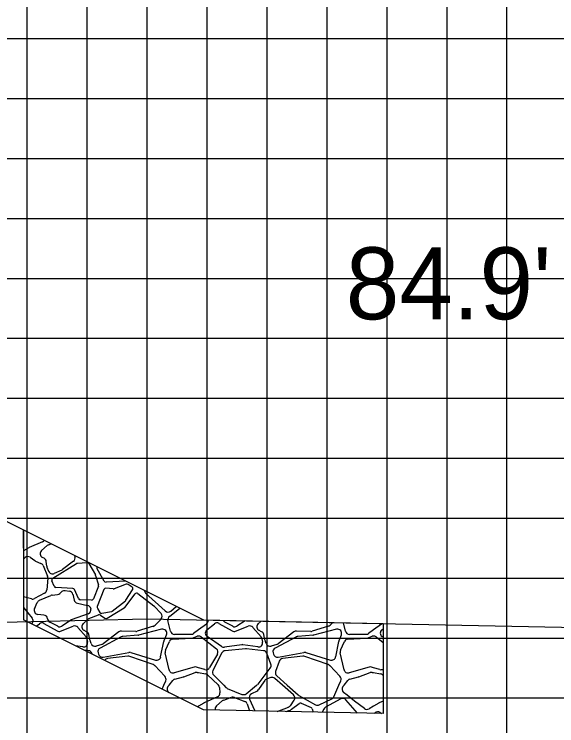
# Model space of a CAD drawing. Extents: x 1785795 to 1786139, y 442591 to 442811.
# Drawn here: x 1786039.83 to 1786048.88, y 442680.2 to 442692.07 of the extents above; entities that cross this region are included whole.
import ezdxf

# ---------------------------------------------------------------- set-up
doc = ezdxf.new("R2010")
doc.units = 0
for name, color, linetype in [('D_Roadway_Centerline', 7, 'Continuous'), ('D_Roadway_SlopeLines', 7, 'Continuous'), ('D_Text_Standard', 7, 'Continuous'), ('MAJOR', 7, 'Continuous'), ('MINOR', 7, 'Continuous'), ('S_Roadway_Centerline', 7, 'Continuous')]:
    doc.layers.add(name, color=color, linetype=linetype)

msp = doc.modelspace()

# ---------------------------------------------------------------- linework, layer by layer
at = {"layer": 'D_Roadway_Centerline'}
msp.add_lwpolyline([(1785883.536, 442683.648), (1785933.236, 442708.498), (1785938.052, 442710.906), (1785941.052, 442711.026), (1785949.052, 442711.346), (1785961.052, 442711.61), (1785973.052, 442711.874), (1785981.052, 442711.554), (1785984.052, 442711.434), (1785988.802, 442709.059), (1786042.988, 442681.966)], dxfattribs=at)
at = {"layer": 'D_Roadway_SlopeLines'}
for p, q in [((1786040.305, 442683.272), (1786040.082, 442683.173)), ((1786040.075, 442683.169), (1786039.988, 442683.117)), ((1786040.289, 442683.123), (1786040.385, 442683.207)), ((1786040.408, 442683.221), (1786040.451, 442683.235)), ((1786040.841, 442683.04), (1786040.847, 442683.022)), ((1786039.988, 442682.983), (1786040.015, 442683.007)), ((1786040.1, 442683.012), (1786040.178, 442682.956)), ((1786040.19, 442682.949), (1786040.28, 442682.91)), ((1786040.332, 442682.996), (1786040.302, 442683.011)), ((1786040.375, 442682.865), (1786040.368, 442682.941)), ((1786040.823, 442682.945), (1786040.639, 442682.806)), ((1786040.89, 442682.911), (1786041.045, 442682.924)), ((1786040.315, 442682.874), (1786040.389, 442682.696)), ((1786040.409, 442682.777), (1786040.381, 442682.844)), ((1786040.477, 442682.662), (1786040.875, 442682.906)), ((1786040.626, 442682.798), (1786040.5, 442682.742)), ((1786041.077, 442682.907), (1786041.189, 442682.718)), ((1786041.333, 442682.614), (1786041.215, 442682.821)), ((1786041.192, 442682.71), (1786041.24, 442682.552)), ((1786040.394, 442682.664), (1786040.376, 442682.468)), ((1786040.5, 442682.53), (1786040.463, 442682.619)), ((1786041.693, 442682.614), (1786041.365, 442682.596)), ((1786041.702, 442682.562), (1786041.5, 442682.487)), ((1786041.8, 442682.514), (1786041.733, 442682.559)), ((1786040.812, 442682.493), (1786040.53, 442682.509)), ((1786040.592, 442682.407), (1786040.63, 442682.439)), ((1786040.681, 442682.455), (1786040.753, 442682.447)), ((1786040.907, 442682.322), (1786040.841, 442682.472)), ((1786041.239, 442682.529), (1786041.155, 442682.317)), ((1786041.329, 442682.475), (1786041.219, 442682.19)), ((1786041.485, 442682.485), (1786041.364, 442682.497)), ((1786041.695, 442682.296), (1786041.809, 442682.467)), ((1786040.12, 442682.317), (1786039.988, 442682.352)), ((1786040.34, 442682.414), (1786040.17, 442682.323)), ((1786040.255, 442682.294), (1786040.447, 442682.375)), ((1786040.465, 442682.379), (1786040.556, 442682.391)), ((1786040.813, 442682.394), (1786040.834, 442682.297)), ((1786041.677, 442682.176), (1786041.849, 442682.4)), ((1786041.897, 442682.407), (1786042.163, 442682.203)), ((1786042.026, 442682.413), (1786042.354, 442682.116)), ((1786040.173, 442682.154), (1786040.218, 442682.259)), ((1786040.887, 442682.245), (1786041.058, 442682.21)), ((1786041.122, 442682.296), (1786040.937, 442682.302)), ((1786041.469, 442682.112), (1786041.688, 442682.288)), ((1786042.167, 442682.199), (1786042.282, 442682.074)), ((1786039.988, 442682.173), (1786040.133, 442681.995)), ((1786041.11, 442682.158), (1786041.113, 442682.147)), ((1786041.222, 442682.16), (1786041.262, 442682.093)), ((1786041.297, 442682.077), (1786041.454, 442682.105)), ((1786041.384, 442681.994), (1786041.668, 442682.167)), ((1786042.421, 442682.025), (1786042.595, 442682.163)), ((1786042.444, 442682.115), (1786042.533, 442682.193)), ((1786040.33, 442682.048), (1786040.228, 442682.059)), ((1786040.391, 442681.984), (1786040.39, 442681.988)), ((1786040.788, 442681.966), (1786040.629, 442681.864)), ((1786041.069, 442682.067), (1786040.802, 442681.973)), ((1786040.984, 442681.904), (1786041.069, 442681.981)), ((1786041.08, 442681.988), (1786041.242, 442682.051)), ((1786041.274, 442682.047), (1786041.346, 442681.995)), ((1786042.282, 442681.981), (1786042.184, 442681.878)), ((1786042.988, 442681.966), (1786045.988, 442681.905)), ((1786040.2, 442681.86), (1786040.253, 442681.903)), ((1786040.33, 442681.909), (1786040.548, 442681.783)), ((1786040.56, 442681.861), (1786040.427, 442681.931)), ((1786040.607, 442681.779), (1786040.818, 442681.862)), ((1786040.895, 442681.843), (1786041.032, 442681.683)), ((1786042.154, 442681.86), (1786041.884, 442681.778)), ((1786042.44, 442681.778), (1786042.397, 442681.955)), ((1786043.04, 442681.897), (1786042.906, 442681.799)), ((1786043.046, 442681.802), (1786043.172, 442681.903)), ((1786043.249, 442681.909), (1786043.466, 442681.783)), ((1786043.479, 442681.861), (1786043.346, 442681.931)), ((1786043.526, 442681.779), (1786043.736, 442681.862)), ((1786043.685, 442681.952), (1786043.547, 442681.864)), ((1786043.813, 442681.843), (1786043.951, 442681.683)), ((1786043.903, 442681.904), (1786043.95, 442681.947)), ((1786045.073, 442681.86), (1786044.803, 442681.778)), ((1786045.145, 442681.922), (1786045.102, 442681.878)), ((1786045.359, 442681.778), (1786045.325, 442681.919)), ((1786045.959, 442681.897), (1786045.825, 442681.799)), ((1786045.988, 442681.905), (1786045.988, 442680.405)), ((1786041.042, 442681.77), (1786040.998, 442681.793)), ((1786041.096, 442681.632), (1786041.077, 442681.724)), ((1786041.579, 442681.767), (1786041.317, 442681.57)), ((1786041.862, 442681.775), (1786041.622, 442681.781)), ((1786042.292, 442681.81), (1786041.909, 442681.715)), ((1786042.785, 442681.726), (1786042.506, 442681.726)), ((1786042.906, 442681.799), (1786042.825, 442681.74)), ((1786043.96, 442681.77), (1786043.917, 442681.793)), ((1786044.014, 442681.632), (1786043.996, 442681.724)), ((1786044.498, 442681.767), (1786044.236, 442681.57)), ((1786044.781, 442681.775), (1786044.541, 442681.781)), ((1786045.211, 442681.81), (1786044.828, 442681.715)), ((1786045.704, 442681.726), (1786045.425, 442681.726)), ((1786045.825, 442681.799), (1786045.744, 442681.74)), ((1786045.965, 442681.802), (1786045.988, 442681.82)), ((1786041.047, 442681.65), (1786041.057, 442681.596)), ((1786041.116, 442681.572), (1786041.098, 442681.623)), ((1786041.62, 442681.685), (1786041.266, 442681.498)), ((1786041.898, 442681.713), (1786041.646, 442681.692)), ((1786042.276, 442681.35), (1786042.328, 442681.609)), ((1786042.332, 442681.622), (1786042.372, 442681.717)), ((1786042.358, 442681.463), (1786042.422, 442681.607)), ((1786042.481, 442681.648), (1786042.783, 442681.661)), ((1786042.803, 442681.664), (1786042.887, 442681.694)), ((1786042.951, 442681.684), (1786043.206, 442681.486)), ((1786043.292, 442681.525), (1786043.05, 442681.692)), ((1786043.966, 442681.65), (1786043.976, 442681.596)), ((1786044.035, 442681.572), (1786044.017, 442681.623)), ((1786044.539, 442681.685), (1786044.185, 442681.498)), ((1786044.817, 442681.713), (1786044.565, 442681.692)), ((1786045.195, 442681.35), (1786045.247, 442681.609)), ((1786045.251, 442681.622), (1786045.29, 442681.717)), ((1786045.276, 442681.463), (1786045.341, 442681.607)), ((1786045.4, 442681.648), (1786045.702, 442681.661)), ((1786045.722, 442681.664), (1786045.805, 442681.694)), ((1786045.87, 442681.684), (1786045.988, 442681.593)), ((1786045.988, 442681.679), (1786045.969, 442681.692)), ((1786040.98, 442681.517), (1786040.848, 442681.536)), ((1786041.297, 442681.559), (1786041.201, 442681.53)), ((1786043.629, 442681.554), (1786043.34, 442681.514)), ((1786043.691, 442681.487), (1786043.351, 442681.453)), ((1786043.899, 442681.517), (1786043.648, 442681.554)), ((1786043.989, 442681.454), (1786043.706, 442681.487)), ((1786044.215, 442681.559), (1786044.12, 442681.53)), ((1786041.071, 442681.454), (1786040.994, 442681.463)), ((1786041.133, 442681.394), (1786041.127, 442681.411)), ((1786041.232, 442681.419), (1786041.238, 442681.396)), ((1786041.316, 442681.347), (1786041.744, 442681.424)), ((1786041.776, 442681.422), (1786042.19, 442681.298)), ((1786042.416, 442681.136), (1786042.353, 442681.42)), ((1786043.224, 442681.398), (1786043.092, 442681.171)), ((1786043.297, 442681.416), (1786043.148, 442681.124)), ((1786044.115, 442681.229), (1786044.045, 442681.411)), ((1786044.151, 442681.419), (1786044.157, 442681.396)), ((1786044.235, 442681.347), (1786044.663, 442681.424)), ((1786044.695, 442681.422), (1786045.109, 442681.298)), ((1786045.335, 442681.136), (1786045.272, 442681.42)), ((1786041.73, 442681.36), (1786041.391, 442681.321)), ((1786042.152, 442681.221), (1786041.76, 442681.356)), ((1786044.253, 442681.276), (1786044.192, 442681.108)), ((1786044.649, 442681.36), (1786044.31, 442681.321)), ((1786045.071, 442681.221), (1786044.679, 442681.356)), ((1786042.347, 442681.026), (1786042.179, 442681.204)), ((1786042.835, 442681.18), (1786042.501, 442681.085)), ((1786042.906, 442681.17), (1786042.873, 442681.18)), ((1786043.014, 442681.14), (1786042.906, 442681.17)), ((1786043.9, 442680.897), (1786044.105, 442681.163)), ((1786045.266, 442681.026), (1786045.098, 442681.204)), ((1786045.754, 442681.18), (1786045.42, 442681.085)), ((1786045.825, 442681.17), (1786045.791, 442681.18)), ((1786045.933, 442681.14), (1786045.825, 442681.17)), ((1786042.514, 442680.98), (1786042.655, 442681.019)), ((1786042.66, 442681.02), (1786042.852, 442681.089)), ((1786042.887, 442681.092), (1786042.906, 442681.088)), ((1786042.906, 442681.088), (1786043.023, 442681.068)), ((1786043.057, 442681.051), (1786043.234, 442680.886)), ((1786043.161, 442681.045), (1786043.328, 442680.877)), ((1786044.211, 442681.034), (1786044.387, 442680.877)), ((1786045.432, 442680.98), (1786045.574, 442681.019)), ((1786045.579, 442681.02), (1786045.771, 442681.089)), ((1786045.805, 442681.092), (1786045.825, 442681.088)), ((1786045.825, 442681.088), (1786045.941, 442681.068)), ((1786045.976, 442681.051), (1786045.988, 442681.04)), ((1786042.328, 442680.877), (1786042.361, 442680.952)), ((1786042.416, 442680.877), (1786042.478, 442680.956)), ((1786044.013, 442680.958), (1786043.958, 442680.877)), ((1786044.115, 442681.005), (1786044.05, 442680.985)), ((1786044.31, 442680.877), (1786044.18, 442680.991)), ((1786045.247, 442680.877), (1786045.279, 442680.952)), ((1786045.335, 442680.877), (1786045.397, 442680.956)), ((1786042.299, 442680.81), (1786042.328, 442680.877)), ((1786042.398, 442680.854), (1786042.416, 442680.877)), ((1786043.256, 442680.842), (1786043.264, 442680.751)), ((1786043.328, 442680.877), (1786043.365, 442680.84)), ((1786043.387, 442680.825), (1786043.631, 442680.725)), ((1786043.7, 442680.735), (1786043.877, 442680.877)), ((1786043.883, 442680.781), (1786043.791, 442680.735)), ((1786043.877, 442680.877), (1786043.888, 442680.886)), ((1786043.958, 442680.877), (1786043.908, 442680.804)), ((1786044.49, 442680.719), (1786044.31, 442680.877)), ((1786044.387, 442680.877), (1786044.568, 442680.715)), ((1786045.164, 442680.685), (1786045.247, 442680.877)), ((1786045.317, 442680.854), (1786045.335, 442680.877)), ((1786042.417, 442680.752), (1786042.409, 442680.758)), ((1786043.224, 442680.682), (1786043.001, 442680.583)), ((1786043.327, 442680.631), (1786043.46, 442680.676)), ((1786043.507, 442680.675), (1786043.68, 442680.608)), ((1786044.58, 442680.706), (1786044.86, 442680.553)), ((1786045.388, 442680.71), (1786045.328, 442680.758)), ((1786045.508, 442680.613), (1786045.388, 442680.71)), ((1786042.994, 442680.579), (1786042.906, 442680.527)), ((1786043.208, 442680.534), (1786043.304, 442680.618)), ((1786043.72, 442680.566), (1786043.759, 442680.451)), ((1786043.759, 442680.646), (1786043.84, 442680.461)), ((1786044.439, 442680.536), (1786044.502, 442680.63)), ((1786044.461, 442680.478), (1786044.588, 442680.573)), ((1786044.622, 442680.577), (1786044.784, 442680.505)), ((1786044.922, 442680.551), (1786045.131, 442680.65)), ((1786045.28, 442680.648), (1786045.026, 442680.509)), ((1786045.561, 442680.414), (1786045.364, 442680.634)), ((1786045.676, 442680.488), (1786045.51, 442680.611)), ((1786045.913, 442680.579), (1786045.825, 442680.527)), ((1786045.988, 442680.613), (1786045.92, 442680.583)), ((1786042.906, 442680.527), (1786042.888, 442680.516)), ((1786044.217, 442680.441), (1786044.406, 442680.51)), ((1786044.37, 442680.438), (1786044.415, 442680.454)), ((1786044.804, 442680.482), (1786044.817, 442680.429)), ((1786044.997, 442680.479), (1786044.971, 442680.426)), ((1786045.825, 442680.527), (1786045.751, 442680.484)), ((1786045.842, 442680.408), (1786045.853, 442680.418)), ((1786045.937, 442680.422), (1786045.96, 442680.406))]:
    msp.add_line(p, q, dxfattribs=at)
for points in [[(1785984.052, 442711.434), (1786042.988, 442681.966)], [(1786039.988, 442683.162), (1786039.988, 442683.466), (1786039.988, 442681.966)], [(1786045.988, 442680.405), (1786042.988, 442680.466), (1786039.988, 442681.966)]]:
    msp.add_lwpolyline(points, dxfattribs=at)
for centre, major_axis, start_param, end_param in [((1786040.278, 442683.334), (0, 0.0683), 3.559817, 4.077835), ((1786040.11, 442683.11), (0, 0.0683), 0.418224, 0.534955), ((1786040.43, 442683.156), (0, 0.0683), 0.321751, 0.71883), ((1786040.06, 442682.956), (0, 0.0683), 5.668522, 7.003256), ((1786040.334, 442683.072), (0, -0.0683), 3.860423, 5.799738), ((1786040.218, 442683.012), (0, -0.0683), 5.668522, 5.870775), ((1786040.252, 442682.848), (0, 0.0683), 5.104729, 5.870775), ((1786040.3, 442682.935), (0, 0.0683), 4.803049, 5.799738), ((1786040.782, 442683), (0, 0.0683), 3.787712, 5.039487), ((1786040.893, 442682.877), (0, 0.0342), 0.081452, 0.550676), ((1786041.048, 442682.89), (0, 0.0342), 5.244893, 6.364637), ((1786040.443, 442682.871), (0, -0.0683), 4.803049, 5.120538), ((1786040.598, 442682.86), (0, -0.0683), 0.416439, 0.646119), ((1786041.244, 442682.838), (0, -0.0342), 4.244764, 5.232357), ((1786040.326, 442682.67), (0, 0.0683), 4.621729, 5.104729), ((1786040.472, 442682.805), (0, -0.0683), 5.120538, 6.699624), ((1786041.159, 442682.7), (0, 0.0342), 5.00783, 5.244893), ((1786040.495, 442682.632), (0, -0.0342), 3.692268, 5.10718), ((1786041.208, 442682.542), (0, 0.0342), 4.331883, 5.00783), ((1786041.363, 442682.631), (0, -0.0342), 5.232357, 6.335377), ((1786041.714, 442682.53), (0, 0.0342), 5.695183, 6.640689), ((1786040.308, 442682.474), (0, -0.0683), 0.489957, 1.480136), ((1786040.532, 442682.543), (0, -0.0342), 5.10718, 6.225111), ((1786040.674, 442682.387), (0, 0.0683), 6.183517, 6.987679), ((1786040.746, 442682.379), (0, 0.0683), 4.928939, 6.183517), ((1786040.81, 442682.459), (0, 0.0342), 5.126896, 6.225111), ((1786041.361, 442682.463), (0, 0.0342), 6.185932, 7.487587), ((1786041.488, 442682.519), (0, -0.0342), 6.185932, 6.640689), ((1786041.781, 442682.486), (0, -0.0342), 0.982794, 2.55359), ((1786042.071, 442682.464), (0, 0.0683), 1.647694, 2.406418), ((1786040.138, 442682.383), (0, -0.0683), 6.025862, 6.773143), ((1786040.473, 442682.312), (0, 0.0683), 0.124355, 0.394791), ((1786040.548, 442682.459), (0, -0.0683), 0.124355, 0.704494), ((1786040.938, 442682.336), (0, -0.0342), 5.126896, 6.25041), ((1786041.123, 442682.33), (0, -0.0342), 6.25041, 7.473475), ((1786041.876, 442682.379), (0, 0.0342), 5.630339, 7.201135), ((1786040.281, 442682.231), (0, 0.0683), 0.394791, 1.157466), ((1786040.901, 442682.312), (0, -0.0683), 4.928939, 6.08014), ((1786041.044, 442682.143), (0, 0.0683), 4.941621, 6.08014), ((1786041.667, 442682.315), (0, -0.0342), 0.676737, 0.982794), ((1786042.142, 442682.176), (0, 0.0342), 5.459199, 5.630339), ((1786040.235, 442682.127), (0, -0.0683), 4.299059, 6.17752), ((1786041.046, 442682.132), (0, 0.0683), 3.480291, 4.941621), ((1786041.251, 442682.178), (0, 0.0342), 1.204402, 2.105751), ((1786041.291, 442682.11), (0, -0.0342), 5.247344, 6.461278), ((1786041.448, 442682.139), (0, -0.0342), 0.178093, 0.676737), ((1786041.65, 442682.197), (0, -0.0342), 0.547562, 0.91795), ((1786042.399, 442682.167), (0, -0.0683), 5.54801, 7.003068), ((1786040.081, 442681.952), (0, 0.0683), 3.813083, 5.401291), ((1786040.323, 442681.98), (0, 0.0683), 4.831818, 6.17752), ((1786040.459, 442681.992), (0, -0.0683), 4.831818, 5.797153), ((1786040.825, 442681.909), (0, 0.0683), 0.338698, 0.570383), ((1786041.092, 442681.956), (0, 0.0342), 0.369906, 0.736656), ((1786041.254, 442682.019), (0, 0.0342), 5.662936, 6.653091), ((1786041.366, 442682.023), (0, -0.0342), 5.662936, 6.830748), ((1786042.232, 442682.028), (0, 0.0683), 3.950796, 5.459199), ((1786042.464, 442681.971), (0, -0.0683), 3.811328, 4.949439), ((1786042.999, 442681.952), (0, 0.0683), 3.773738, 4.899598), ((1786043.377, 442681.992), (0, -0.0683), 5.199293, 5.797153), ((1786040.296, 442681.85), (0, 0.0683), 5.75839, 6.961848), ((1786040.592, 442681.921), (0, -0.0683), 5.797153, 6.853569), ((1786040.843, 442681.799), (0, 0.0683), 5.421015, 6.659146), ((1786041.03, 442681.854), (0, -0.0683), 3.878249, 5.800672), ((1786042.134, 442681.925), (0, -0.0683), 0.294937, 0.809203), ((1786043.215, 442681.85), (0, 0.0683), 5.75839, 6.961848), ((1786043.511, 442681.921), (0, -0.0683), 5.797153, 6.853569), ((1786043.761, 442681.799), (0, 0.0683), 5.421015, 6.659146), ((1786043.949, 442681.854), (0, -0.0683), 3.878249, 5.800672), ((1786045.053, 442681.925), (0, -0.0683), 0.294937, 0.809203), ((1786045.918, 442681.952), (0, 0.0683), 3.773738, 3.96556), ((1786040.582, 442681.842), (0, -0.0683), 5.75839, 6.659146), ((1786041.01, 442681.71), (0, 0.0683), 4.915434, 5.800672), ((1786041.62, 442681.713), (0, 0.0683), 6.255795, 6.928761), ((1786041.864, 442681.843), (0, -0.0683), 6.255795, 6.578122), ((1786042.309, 442681.744), (0, -0.0683), 1.177705, 3.383486), ((1786042.506, 442681.794), (0, -0.0683), 4.949439, 6.284735), ((1786042.785, 442681.795), (0, -0.0683), 0.001549, 0.632145), ((1786043.089, 442681.748), (0, -0.0683), 3.820255, 5.679955), ((1786043.501, 442681.842), (0, -0.0683), 5.75839, 6.659146), ((1786043.929, 442681.71), (0, 0.0683), 4.915434, 5.800672), ((1786044.539, 442681.713), (0, 0.0683), 6.255795, 6.928761), ((1786044.783, 442681.843), (0, -0.0683), 6.255795, 6.578122), ((1786045.227, 442681.744), (0, -0.0683), 1.177705, 3.383486), ((1786045.425, 442681.794), (0, -0.0683), 4.949439, 6.284735), ((1786045.704, 442681.795), (0, -0.0683), 0.001549, 0.632145), ((1786046.007, 442681.748), (0, -0.0683), 3.820255, 5.679955), ((1786040.98, 442681.638), (0, 0.0683), 4.892242, 5.421015), ((1786041.163, 442681.645), (0, -0.0683), 4.915434, 5.053368), ((1786041.652, 442681.624), (0, 0.0683), 0.083141, 0.485227), ((1786041.893, 442681.782), (0, -0.0683), 0.083141, 0.241894), ((1786042.395, 442681.596), (0, 0.0683), 1.177705, 1.37369), ((1786042.484, 442681.58), (0, 0.0683), 0.042528, 1.152572), ((1786042.78, 442681.729), (0, -0.0683), 0.042528, 0.339293), ((1786042.909, 442681.63), (0, 0.0683), 0.046753, 0.339293), ((1786042.909, 442681.63), (0, 0.0683), 5.625297, 6.329939), ((1786043.899, 442681.638), (0, 0.0683), 4.892242, 5.421015), ((1786044.081, 442681.645), (0, -0.0683), 4.915434, 5.053368), ((1786044.57, 442681.624), (0, 0.0683), 0.083141, 0.485227), ((1786044.811, 442681.782), (0, -0.0683), 0.083141, 0.241894), ((1786045.314, 442681.596), (0, 0.0683), 1.177705, 1.37369), ((1786045.403, 442681.58), (0, 0.0683), 0.042528, 1.152572), ((1786045.699, 442681.729), (0, -0.0683), 0.042528, 0.339293), ((1786045.828, 442681.63), (0, 0.0683), 0.046753, 0.339293), ((1786045.828, 442681.63), (0, 0.0683), 5.625297, 6.329939), ((1786040.99, 442681.584), (0, 0.0683), 2.993743, 4.892242), ((1786041.181, 442681.595), (0, -0.0683), 5.053368, 6.584804), ((1786041.298, 442681.438), (0, 0.0683), 0.485227, 1.841743), ((1786041.276, 442681.625), (0, -0.0683), 0.301619, 0.645576), ((1786043.165, 442681.432), (0, 0.0683), 4.185762, 5.625297), ((1786043.331, 442681.581), (0, -0.0683), 5.679955, 6.421825), ((1786043.638, 442681.486), (0, 0.0683), 6.135336, 6.421825), ((1786043.698, 442681.419), (0, 0.0683), 6.170034, 6.380912), ((1786043.909, 442681.584), (0, 0.0683), 2.993743, 4.892242), ((1786044.099, 442681.595), (0, -0.0683), 5.053368, 6.584804), ((1786044.217, 442681.438), (0, 0.0683), 0.485227, 1.841743), ((1786044.195, 442681.625), (0, -0.0683), 0.301619, 0.645576), ((1786041.063, 442681.386), (0, 0.0683), 5.07759, 6.170034), ((1786041.304, 442681.415), (0, -0.0683), 4.983336, 6.460411), ((1786041.756, 442681.357), (0, 0.0683), 5.991139, 6.460411), ((1786042.42, 442681.435), (0, -0.0683), 4.294165, 4.928939), ((1786043.358, 442681.385), (0, 0.0683), 0.097727, 1.099019), ((1786043.982, 442681.386), (0, 0.0683), 5.07759, 6.170034), ((1786044.223, 442681.415), (0, -0.0683), 4.983336, 6.460411), ((1786044.675, 442681.357), (0, 0.0683), 5.991139, 6.460411), ((1786045.339, 442681.435), (0, -0.0683), 4.294165, 4.928939), ((1786041.399, 442681.253), (0, 0.0683), 0.113874, 1.005419), ((1786041.738, 442681.292), (0, 0.0683), 5.950458, 6.397059), ((1786042.21, 442681.363), (0, -0.0683), 5.991139, 7.656876), ((1786044.317, 442681.253), (0, 0.0683), 0.113874, 1.223118), ((1786044.657, 442681.292), (0, 0.0683), 5.950458, 6.397059), ((1786045.128, 442681.363), (0, -0.0683), 5.991139, 7.656876), ((1786042.13, 442681.156), (0, 0.0683), 5.472885, 5.950458), ((1786042.483, 442681.15), (0, -0.0683), 4.928939, 6.561485), ((1786042.854, 442681.114), (0, 0.0683), 6.004886, 6.561485), ((1786043.033, 442681.205), (0, -0.0683), 6.004886, 7.327354), ((1786044.051, 442681.204), (0, -0.0683), 0.911486, 1.935998), ((1786045.048, 442681.156), (0, 0.0683), 5.472885, 5.950458), ((1786045.401, 442681.15), (0, -0.0683), 4.928939, 6.561485), ((1786045.773, 442681.114), (0, 0.0683), 6.004886, 6.561485), ((1786045.952, 442681.205), (0, -0.0683), 6.004886, 6.839552), ((1786042.298, 442680.979), (0, -0.0683), 1.163165, 2.331293), ((1786042.637, 442681.085), (0, -0.0683), 0.266252, 0.343024), ((1786042.875, 442681.024), (0, 0.0683), 6.110994, 6.626209), ((1786043.011, 442681.001), (0, 0.0683), 5.534807, 6.110994), ((1786043.209, 442681.093), (0, 0.0683), 1.099019, 2.356194), ((1786044.135, 442680.939), (0, 0.0683), 5.565745, 6.57742), ((1786044.257, 442681.085), (0, 0.0683), 1.223118, 2.412764), ((1786045.217, 442680.979), (0, -0.0683), 1.163165, 2.331293), ((1786045.556, 442681.085), (0, -0.0683), 0.266252, 0.343024), ((1786045.794, 442681.024), (0, 0.0683), 6.110994, 6.626209), ((1786045.93, 442681.001), (0, 0.0683), 5.534807, 6.110994), ((1786042.532, 442680.914), (0, 0.0683), 0.266252, 0.90675), ((1786043.846, 442680.939), (0, -0.0683), 0.674741, 0.911486), ((1786044.07, 442680.919), (0, 0.0683), 0.294235, 0.97362), ((1786045.45, 442680.914), (0, 0.0683), 0.266252, 0.90675), ((1786042.452, 442680.812), (0, -0.0683), 4.048343, 5.608444), ((1786043.188, 442680.836), (0, 0.0683), 5.35086, 5.534807), ((1786043.188, 442680.836), (0, 0.0683), 4.803049, 5.35086), ((1786043.413, 442680.889), (0, -0.0683), 5.497787, 5.893869), ((1786043.852, 442680.842), (0, -0.0683), 0.463648, 0.97362), ((1786045.37, 442680.812), (0, -0.0683), 4.048343, 5.608444), ((1786043.196, 442680.745), (0, 0.0683), 3.559817, 4.803049), ((1786043.482, 442680.611), (0, 0.0683), 5.917129, 6.604936), ((1786043.657, 442680.788), (0, -0.0683), 5.893869, 6.957926), ((1786043.821, 442680.674), (0, 0.0683), 0.463648, 1.985303), ((1786044.445, 442680.668), (0, -0.0683), 0.977446, 2.424153), ((1786044.613, 442680.766), (0, -0.0683), 5.554357, 5.782172), ((1786045.101, 442680.712), (0, -0.0683), 0.443382, 1.163165), ((1786045.313, 442680.589), (0, 0.0683), 5.44252, 6.785098), ((1786045.345, 442680.657), (0, 0.0683), 5.600869, 5.608444), ((1786043.029, 442680.521), (0, 0.0683), 0.418224, 0.534955), ((1786043.349, 442680.566), (0, 0.0683), 0.321751, 0.71883), ((1786043.656, 442680.544), (0, 0.0683), 5.039487, 5.917129), ((1786044.382, 442680.574), (0, -0.0683), 0.347767, 0.977446), ((1786044.608, 442680.546), (0, 0.0342), 5.866747, 6.924845), ((1786044.892, 442680.613), (0, -0.0683), 5.782172, 6.726567), ((1786045.551, 442680.666), (0, -0.0683), 5.600869, 5.645637), ((1786045.947, 442680.521), (0, 0.0683), 0.418224, 0.534955), ((1786043.253, 442680.482), (0, -0.0683), 3.860423, 5.010275), ((1786043.903, 442680.489), (0, -0.0683), 5.126896, 5.335437), ((1786044.359, 442680.615), (0, -0.171), 0.333945, 0.641659), ((1786044.771, 442680.474), (0, 0.0342), 4.95256, 5.866747), ((1786045.058, 442680.449), (0, 0.0683), 0.501913, 1.108164), ((1786045.717, 442680.543), (0, -0.0683), 5.645637, 6.81814), ((1786045.898, 442680.366), (0, 0.0683), 5.668522, 7.003256)]:
    msp.add_ellipse(centre, major_axis=major_axis, ratio=0.99895, start_param=start_param, end_param=end_param, dxfattribs=at)
at = {"layer": 'MAJOR'}
for p, q in [((1786041.052, 442673.665), (1786041.052, 442718.665)), ((1785821.052, 442688.665), (1786101.052, 442688.665)), ((1785821.052, 442683.665), (1786101.052, 442683.665))]:
    msp.add_line(p, q, dxfattribs=at)
at = {"layer": 'MINOR'}
for p, q in [((1786040.052, 442673.665), (1786040.052, 442718.665)), ((1786042.052, 442673.665), (1786042.052, 442718.665)), ((1786043.052, 442673.665), (1786043.052, 442718.665)), ((1786044.052, 442673.665), (1786044.052, 442718.665)), ((1786045.052, 442673.665), (1786045.052, 442718.665)), ((1786046.052, 442673.665), (1786046.052, 442718.665)), ((1786047.052, 442673.665), (1786047.052, 442718.665)), ((1786048.052, 442673.665), (1786048.052, 442718.665)), ((1785821.052, 442691.665), (1786101.052, 442691.665)), ((1785821.052, 442690.665), (1786101.052, 442690.665)), ((1785821.052, 442689.665), (1786101.052, 442689.665)), ((1785821.052, 442687.665), (1786101.052, 442687.665)), ((1785821.052, 442686.665), (1786101.052, 442686.665)), ((1785821.052, 442685.665), (1786101.052, 442685.665)), ((1785821.052, 442684.665), (1786101.052, 442684.665)), ((1785821.052, 442682.665), (1786101.052, 442682.665)), ((1785821.052, 442681.665), (1786101.052, 442681.665)), ((1785821.052, 442680.665), (1786101.052, 442680.665))]:
    msp.add_line(p, q, dxfattribs=at)
at = {"layer": 'S_Roadway_Centerline'}
msp.add_lwpolyline([(1785931.287, 442682.542), (1785945.812, 442682.061), (1785951.792, 442681.948), (1785960.925, 442682.058), (1785972.421, 442681.984), (1785973.039, 442681.978), (1785973.763, 442681.963), (1785975.204, 442681.998), (1785988.196, 442682.043), (1785993.099, 442681.978), (1785994.683, 442681.884), (1785998.592, 442681.925), (1786012.689, 442681.876), (1786018.161, 442681.813), (1786024.929, 442681.788), (1786034.347, 442681.807), (1786042.047, 442681.986), (1786053.666, 442681.749), (1786054.761, 442681.741), (1786059.545, 442681.801)], dxfattribs=at)

# ---------------------------------------------------------------- texts
at = {"layer": 'D_Text_Standard'}
msp.add_text("84.9'", height=1.2, dxfattribs=at).set_placement((1786045.364, 442686.982))

doc.saveas('drawing.dxf')
